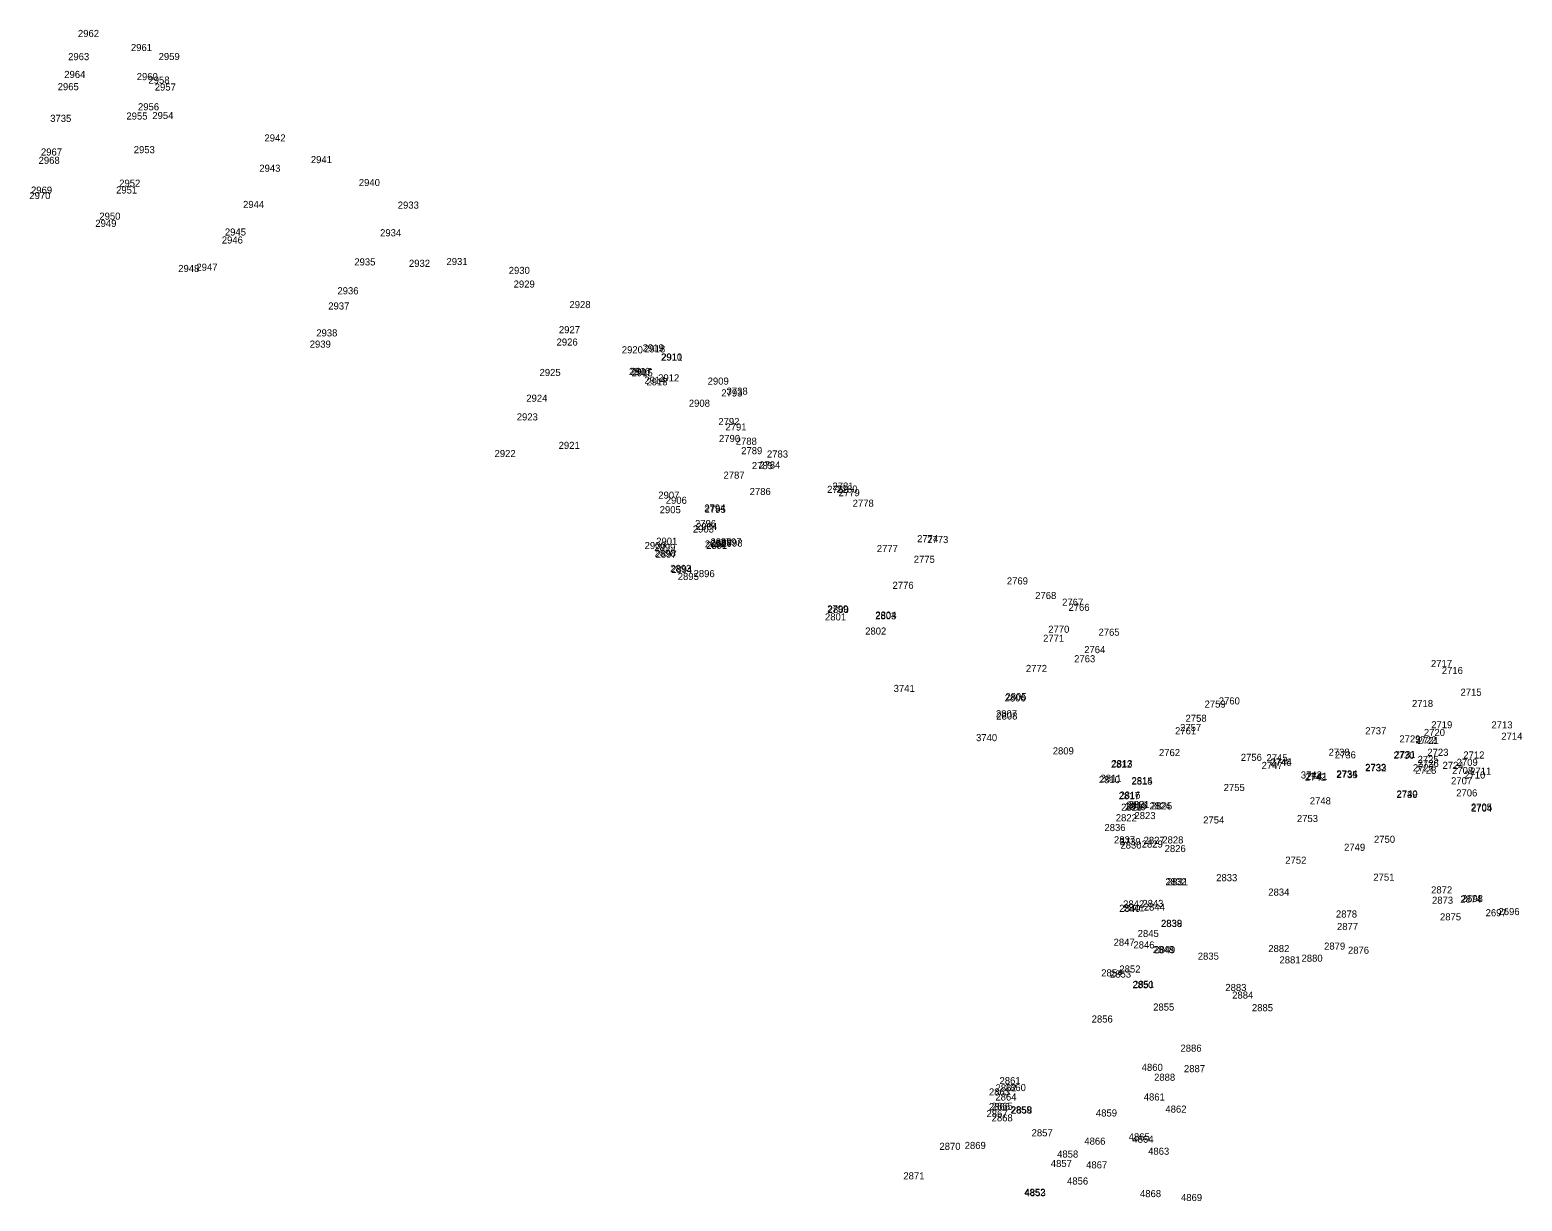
# Model space of a CAD drawing. Extents: x -740053 to -737517, y -1033516 to -1032488.
# Drawn here: x -738879.2 to -738763.4, y -1032654.9 to -1032563.9 of the extents above; entities that cross this region are included whole.
import ezdxf

# ---------------------------------------------------------------- set-up
doc = ezdxf.new("R2010")
doc.units = 0
doc.layers.add('bod-cislo', color=7, linetype='Continuous')

msp = doc.modelspace()

# ---------------------------------------------------------------- texts
at = {"layer": 'bod-cislo'}
for s, p in [('2962', (-738875.43, -1032564.5)), ('2961', (-738871.32, -1032565.59)), ('2963', (-738876.19, -1032566.3)), ('2959', (-738869.17, -1032566.29)), ('2964', (-738876.49, -1032567.68)), ('2960', (-738870.87, -1032567.85)), ('2965', (-738877, -1032568.63)), ('2958', (-738869.96, -1032568.12)), ('2957', (-738869.47, -1032568.66)), ('2956', (-738870.77, -1032570.19)), ('3735', (-738877.58, -1032571.09)), ('2955', (-738871.67, -1032570.91)), ('2954', (-738869.66, -1032570.87)), ('2967', (-738878.3, -1032573.7)), ('2953', (-738871.1, -1032573.52)), ('2942', (-738860.96, -1032572.61)), ('2968', (-738878.48, -1032574.35)), ('2941', (-738857.36, -1032574.29)), ('2943', (-738861.36, -1032574.96)), ('2940', (-738853.64, -1032576.07)), ('2970', (-738879.2, -1032577.08)), ('2969', (-738879.07, -1032576.66)), ('2951', (-738872.47, -1032576.65)), ('2952', (-738872.23, -1032576.12)), ('2944', (-738862.62, -1032577.77)), ('2933', (-738850.62, -1032577.82)), ('2949', (-738874.08, -1032579.24)), ('2950', (-738873.77, -1032578.68)), ('2946', (-738864.27, -1032580.53)), ('2945', (-738864.03, -1032579.91)), ('2934', (-738851.99, -1032579.97)), ('2948', (-738867.65, -1032582.74)), ('2947', (-738866.24, -1032582.64)), ('2935', (-738853.99, -1032582.23)), ('2932', (-738849.75, -1032582.34)), ('2931', (-738846.84, -1032582.2)), ('2930', (-738842.01, -1032582.89)), ('2929', (-738841.63, -1032583.95)), ('2936', (-738855.3, -1032584.47)), ('2937', (-738856.01, -1032585.65)), ('2928', (-738837.3, -1032585.54)), ('2927', (-738838.12, -1032587.49)), ('2939', (-738857.45, -1032588.61)), ('2938', (-738856.94, -1032587.74)), ('2926', (-738838.3, -1032588.45)), ('2920', (-738833.24, -1032589.05)), ('2919', (-738831.62, -1032588.9)), ('2918', (-738831.51, -1032588.98)), ('2910', (-738830.2, -1032589.61)), ('2911', (-738830.17, -1032589.62)), ('2925', (-738839.62, -1032590.81)), ('2916', (-738832.68, -1032590.73)), ('2917', (-738832.56, -1032590.73)), ('2915', (-738832.48, -1032590.83)), ('2914', (-738831.49, -1032591.41)), ('2913', (-738831.33, -1032591.54)), ('2912', (-738830.42, -1032591.23)), ('2909', (-738826.58, -1032591.48)), ('3738', (-738825.11, -1032592.26)), ('2924', (-738840.65, -1032592.81)), ('2908', (-738828.04, -1032593.2)), ('2793', (-738825.52, -1032592.4)), ('2923', (-738841.39, -1032594.26)), ('2792', (-738825.75, -1032594.62)), ('2791', (-738825.2, -1032595.04)), ('2921', (-738838.14, -1032596.47)), ('2790', (-738825.7, -1032595.93)), ('2788', (-738824.4, -1032596.15)), ('2789', (-738823.98, -1032596.88)), ('2922', (-738843.11, -1032597.1)), ('2785', (-738823.15, -1032598.04)), ('2784', (-738822.58, -1032597.99)), ('2783', (-738821.98, -1032597.14)), ('2787', (-738825.35, -1032598.78)), ('2907', (-738830.41, -1032600.33)), ('2786', (-738823.32, -1032600.05)), ('2782', (-738817.31, -1032599.88)), ('2781', (-738816.9, -1032599.63)), ('2780', (-738816.59, -1032599.86)), ('2779', (-738816.42, -1032600.14)), ('2905', (-738830.3, -1032601.46)), ('2906', (-738829.83, -1032600.73)), ('2794', (-738826.84, -1032601.33)), ('2795', (-738826.81, -1032601.43)), ('2778', (-738815.33, -1032600.96)), ('2796', (-738827.56, -1032602.54)), ('2903', (-738827.73, -1032602.96)), ('2904', (-738827.48, -1032602.77)), ('2774', (-738810.33, -1032603.71)), ('2773', (-738809.55, -1032603.78)), ('2900', (-738831.47, -1032604.24)), ('2899', (-738830.72, -1032604.39)), ('2898', (-738830.69, -1032604.83)), ('2897', (-738830.62, -1032604.91)), ('2901', (-738830.57, -1032603.91)), ('2892', (-738826.8, -1032604.12)), ('2891', (-738826.7, -1032604.23)), ('2889', (-738826.36, -1032603.96)), ('2890', (-738826.35, -1032604.07)), ('2797', (-738825.58, -1032603.96)), ('2798', (-738825.51, -1032604.05)), ('2777', (-738813.46, -1032604.48)), ('2893', (-738829.48, -1032606.02)), ('2894', (-738829.42, -1032606.09)), ('2775', (-738810.59, -1032605.31)), ('2895', (-738828.9, -1032606.64)), ('2896', (-738827.67, -1032606.42)), ('2769', (-738803.37, -1032606.99)), ('2776', (-738812.24, -1032607.33)), ('2768', (-738801.17, -1032608.12)), ('2799', (-738817.31, -1032609.16)), ('2800', (-738817.27, -1032609.21)), ('2804', (-738813.57, -1032609.64)), ('2767', (-738799.08, -1032608.64)), ('2766', (-738798.59, -1032609.04)), ('2801', (-738817.48, -1032609.78)), ('2803', (-738813.58, -1032609.7)), ('2770', (-738800.16, -1032610.74)), ('2802', (-738814.36, -1032610.88)), ('2771', (-738800.56, -1032611.44)), ('2765', (-738796.26, -1032610.97)), ('2763', (-738798.15, -1032613.03)), ('2764', (-738797.37, -1032612.32)), ('2772', (-738801.89, -1032613.78)), ('2717', (-738770.47, -1032613.4)), ('2716', (-738769.63, -1032613.94)), ('3741', (-738812.15, -1032615.33)), ('2806', (-738803.54, -1032616.07)), ('2805', (-738803.48, -1032615.97)), ('2759', (-738788.03, -1032616.55)), ('2760', (-738786.93, -1032616.3)), ('2718', (-738771.94, -1032616.5)), ('2715', (-738768.18, -1032615.63)), ('2807', (-738804.22, -1032617.3)), ('2808', (-738804.19, -1032617.47)), ('2758', (-738789.51, -1032617.65)), ('2761', (-738790.32, -1032618.62)), ('2757', (-738789.93, -1032618.37)), ('2737', (-738775.57, -1032618.62)), ('2720', (-738771.02, -1032618.75)), ('2719', (-738770.45, -1032618.15)), ('2713', (-738765.78, -1032618.16)), ('3740', (-738805.76, -1032619.15)), ('2729', (-738772.92, -1032619.25)), ('2722', (-738771.68, -1032619.33)), ('2721', (-738771.51, -1032619.38)), ('2714', (-738765.01, -1032619.04)), ('2809', (-738799.81, -1032620.18)), ('2813', (-738795.26, -1032621.16)), ('2762', (-738791.57, -1032620.31)), ('2756', (-738785.22, -1032620.68)), ('2745', (-738783.23, -1032620.71)), ('2746', (-738782.94, -1032621.06)), ('2744', (-738782.89, -1032621.04)), ('2738', (-738778.41, -1032620.28)), ('2736', (-738777.93, -1032620.49)), ('2730', (-738773.38, -1032620.52)), ('2731', (-738773.3, -1032620.46)), ('2725', (-738771.51, -1032620.84)), ('2726', (-738771.5, -1032621.15)), ('2723', (-738770.75, -1032620.29)), ('2709', (-738768.48, -1032621.07)), ('2712', (-738767.96, -1032620.5)), ('2811', (-738796.11, -1032622.3)), ('2812', (-738795.3, -1032621.22)), ('2747', (-738783.61, -1032621.31)), ('3742', (-738780.57, -1032622.05)), ('2742', (-738780.25, -1032622.21)), ('2741', (-738780.14, -1032622.14)), ('2734', (-738777.81, -1032621.96)), ('2735', (-738777.79, -1032622.02)), ('2733', (-738775.58, -1032621.46)), ('2732', (-738775.56, -1032621.5)), ('2727', (-738771.87, -1032621.49)), ('2728', (-738771.69, -1032621.68)), ('2724', (-738769.57, -1032621.3)), ('2708', (-738768.83, -1032621.7)), ('2710', (-738767.89, -1032622.05)), ('2711', (-738767.43, -1032621.75)), ('2810', (-738796.23, -1032622.41)), ('2814', (-738793.7, -1032622.49)), ('2815', (-738793.7, -1032622.53)), ('2755', (-738786.55, -1032623.02)), ('2740', (-738773.14, -1032623.52)), ('2707', (-738768.91, -1032622.5)), ('2706', (-738768.51, -1032623.44)), ('2817', (-738794.7, -1032623.67)), ('2816', (-738794.64, -1032623.61)), ('2820', (-738794.51, -1032624.55)), ('2819', (-738794.21, -1032624.51)), ('2818', (-738794.11, -1032624.39)), ('2821', (-738793.94, -1032624.34)), ('2824', (-738792.3, -1032624.44)), ('2825', (-738792.18, -1032624.45)), ('2748', (-738779.87, -1032624.06)), ('2739', (-738773.14, -1032623.56)), ('2705', (-738767.37, -1032624.54)), ('2704', (-738767.36, -1032624.62)), ('2822', (-738794.92, -1032625.37)), ('2823', (-738793.47, -1032625.2)), ('2754', (-738788.14, -1032625.54)), ('2753', (-738780.87, -1032625.43)), ('2836', (-738795.8, -1032626.13)), ('2837', (-738795.06, -1032627.08)), ('3739', (-738794.63, -1032627.22)), ('2830', (-738794.56, -1032627.49)), ('2829', (-738792.91, -1032627.41)), ('2827', (-738792.76, -1032627.12)), ('2828', (-738791.31, -1032627.09)), ('2826', (-738791.13, -1032627.76)), ('2749', (-738777.21, -1032627.66)), ('2750', (-738774.89, -1032627.04)), ('2752', (-738781.77, -1032628.66)), ('2832', (-738791.07, -1032630.33)), ('2831', (-738790.94, -1032630.34)), ('2833', (-738787.13, -1032630.02)), ('2751', (-738774.94, -1032629.98)), ('2834', (-738783.09, -1032631.14)), ('2872', (-738770.46, -1032630.97)), ('2840', (-738794.65, -1032632.4)), ('2842', (-738794.35, -1032632.06)), ('2841', (-738794.33, -1032632.36)), ('2843', (-738792.86, -1032632.02)), ('2844', (-738792.75, -1032632.3)), ('2873', (-738770.39, -1032631.77)), ('2874', (-738768.19, -1032631.68)), ('2698', (-738768.08, -1032631.64)), ('2697', (-738766.23, -1032632.74)), ('2696', (-738765.23, -1032632.65)), ('2839', (-738791.42, -1032633.56)), ('2838', (-738791.4, -1032633.58)), ('2878', (-738777.84, -1032632.84)), ('2877', (-738777.76, -1032633.81)), ('2875', (-738769.77, -1032633.06)), ('2847', (-738795.09, -1032635.03)), ('2845', (-738793.22, -1032634.35)), ('2846', (-738793.55, -1032635.24)), ('2848', (-738792.05, -1032635.6)), ('2849', (-738791.95, -1032635.61)), ('2835', (-738788.56, -1032636.11)), ('2882', (-738783.09, -1032635.52)), ('2879', (-738778.76, -1032635.33)), ('2876', (-738776.91, -1032635.65)), ('2854', (-738796.05, -1032637.41)), ('2852', (-738794.64, -1032637.11)), ('2881', (-738782.22, -1032636.4)), ('2880', (-738780.51, -1032636.27)), ('2853', (-738795.37, -1032637.5)), ('2850', (-738793.63, -1032638.33)), ('2851', (-738793.58, -1032638.29)), ('2883', (-738786.42, -1032638.54)), ('2884', (-738785.89, -1032639.13)), ('2855', (-738792.02, -1032640.06)), ('2885', (-738784.36, -1032640.11)), ('2856', (-738796.79, -1032640.99)), ('2886', (-738789.9, -1032643.25)), ('4860', (-738792.91, -1032644.74)), ('2888', (-738791.95, -1032645.51)), ('2887', (-738789.63, -1032644.84)), ('2863', (-738804.76, -1032646.65)), ('2862', (-738804.25, -1032646.33)), ('2861', (-738803.94, -1032645.77)), ('2860', (-738803.53, -1032646.31)), ('2866', (-738804.76, -1032647.79)), ('2865', (-738804.54, -1032647.76)), ('2864', (-738804.26, -1032647.04)), ('4861', (-738792.75, -1032647.04)), ('2867', (-738804.95, -1032648.33)), ('2868', (-738804.55, -1032648.66)), ('2859', (-738803.08, -1032648.03)), ('2858', (-738803.04, -1032648.06)), ('4859', (-738796.46, -1032648.28)), ('4862', (-738791.07, -1032647.98)), ('2857', (-738801.45, -1032649.82)), ('4865', (-738793.92, -1032650.13)), ('2870', (-738808.6, -1032650.87)), ('2869', (-738806.64, -1032650.8)), ('4866', (-738797.36, -1032650.47)), ('4864', (-738793.63, -1032650.32)), ('4863', (-738792.41, -1032651.25)), ('4857', (-738799.96, -1032652.2)), ('4858', (-738799.47, -1032651.47)), ('4867', (-738797.22, -1032652.31)), ('2871', (-738811.4, -1032653.16)), ('4856', (-738798.7, -1032653.56)), ('4852', (-738802.02, -1032654.43)), ('4853', (-738801.99, -1032654.47)), ('4868', (-738793.04, -1032654.54)), ('4869', (-738789.86, -1032654.84))]:
    msp.add_text(s, height=0.55, dxfattribs=at).set_placement(p)

doc.saveas('drawing.dxf')
